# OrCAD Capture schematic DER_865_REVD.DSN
size D
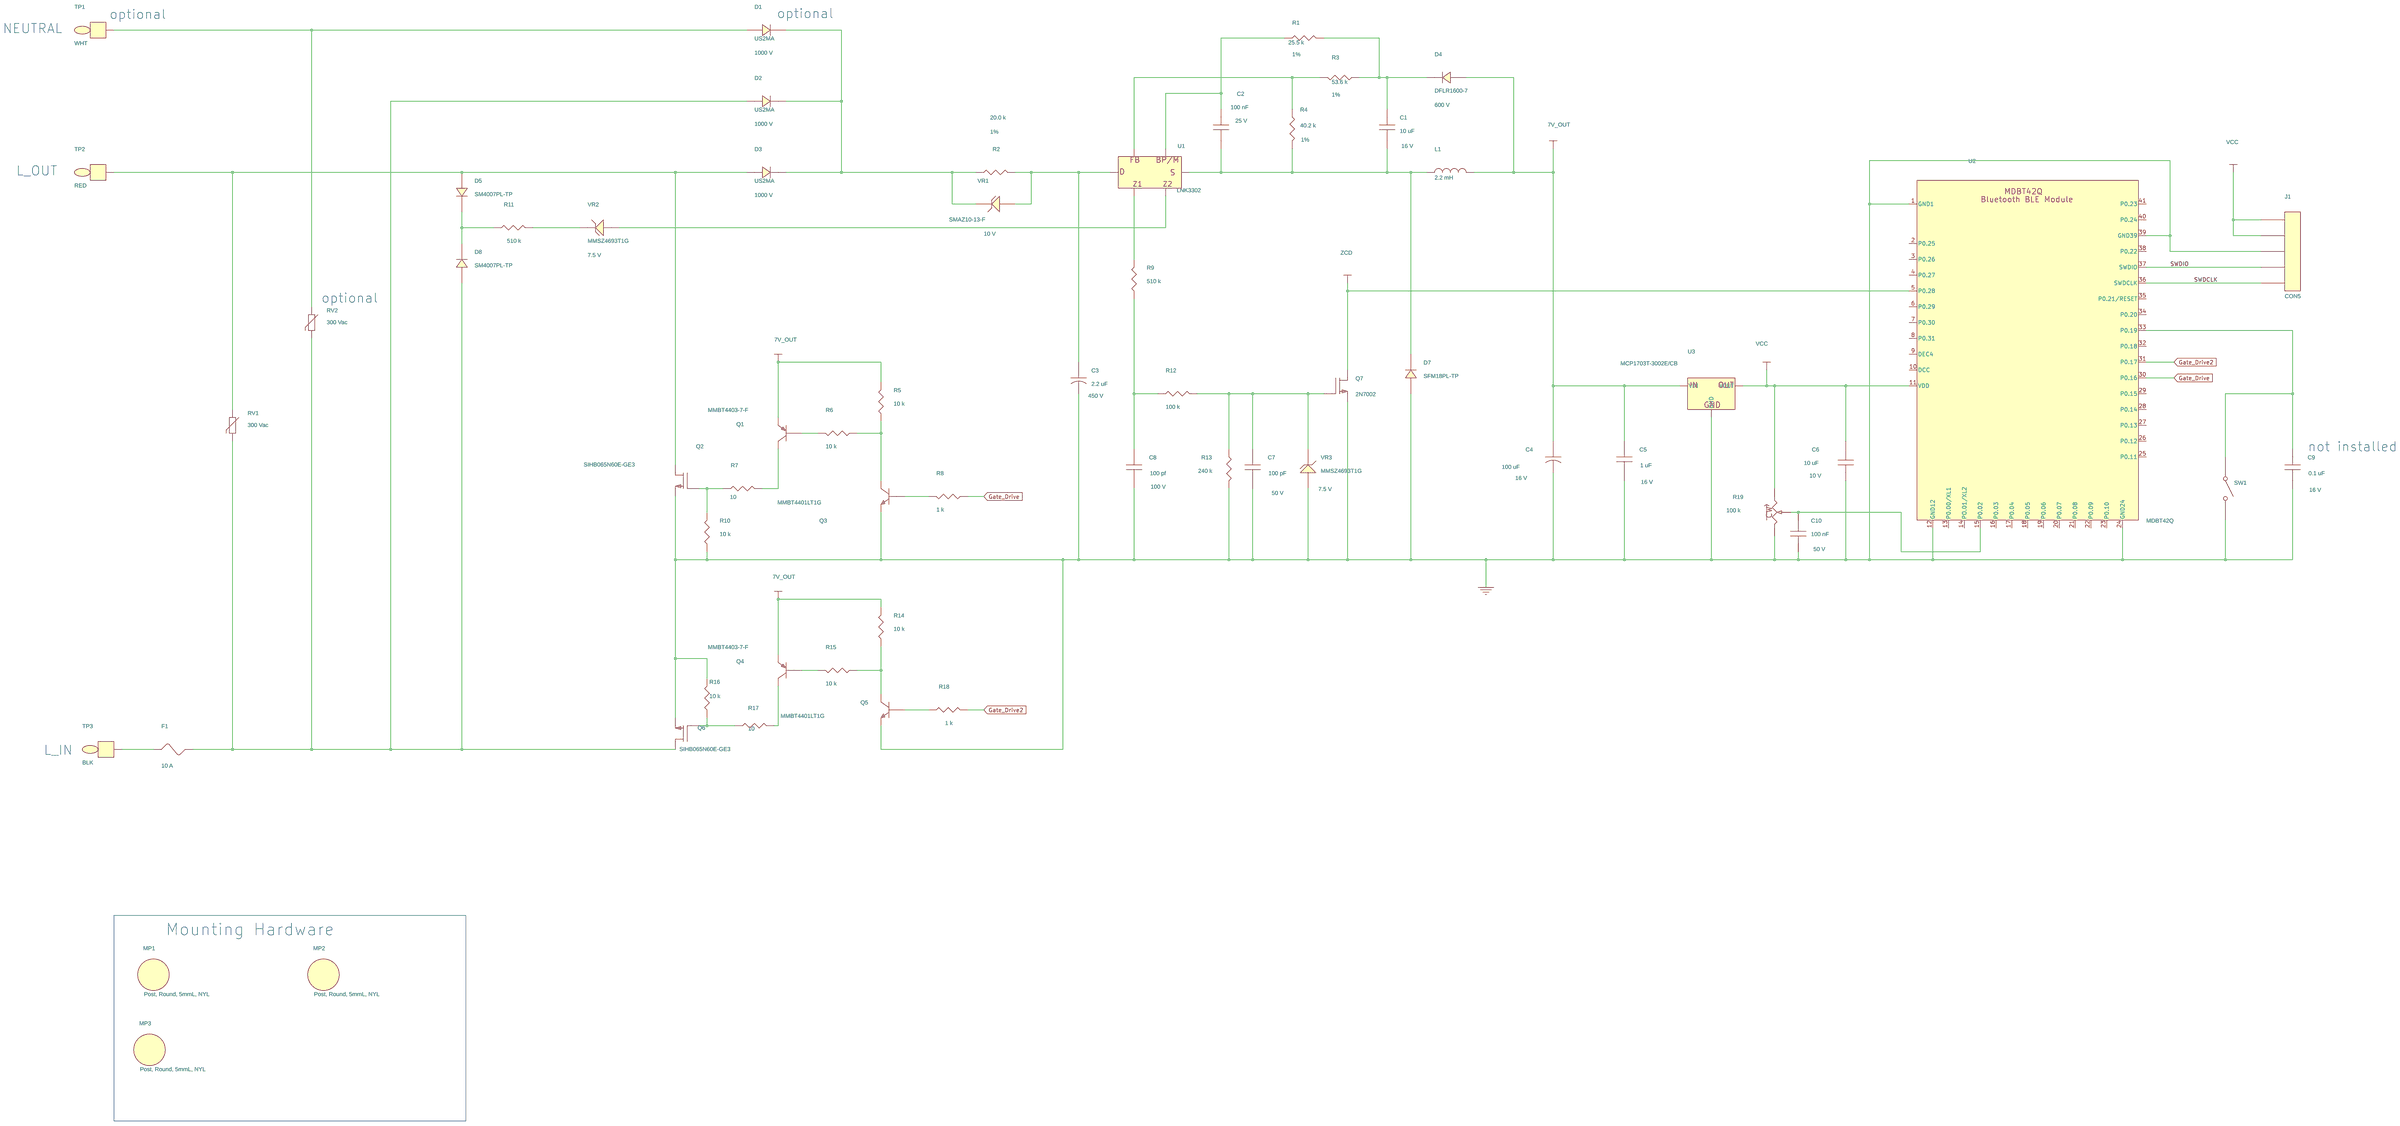
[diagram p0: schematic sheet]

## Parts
C1  10 uF  [pismc0805]
C2  100 nF  [pismc0805]
C3  2.2 uF  [pipolcapclyd320ls140030]
C4  100 uF  [pipolcapcyld250ls100030]
C5  1 uF  [pismc0805]
C6  10 uF  [pismc0805]
C7  100 pF  [pismc0603]
C8  100 pf  [pismc0805]
C9  0.1 uF  [pismc0805]
C10  100 nF  [pismc0603]
D1  US2MA  [pismdo214ac12]
D2  US2MA  [pismdo214ac12]
D3  US2MA  [pismdo214ac12]
D4  DFLR1600-7  [pismddflr120012]
D5  SM4007PL-TP  [pi_sm_sod-123_12]
D7  SFM18PL-TP  [pi_sm_sod-123_12]
D8  SM4007PL-TP  [pi_sm_sod-123_12]
F1  10 A  [pismFuse10p1x3p0]
J1  CON5  [pi_molex_5]
L1  2.2 mH  [pi_choke_2p_ls200d300]
MP1  Post, Round, 5mmL, NYL  [piSRSpacer_d125]
MP2  Post, Round, 5mmL, NYL  [piSRSpacer_d125]
MP3  Post, Round, 5mmL, NYL  [piSRSpacer_d125]
Q1  MMBT4403-7-F  [pismsot23123_1]
Q2  SIHB065N60E-GE3  [pismdd2pak]
Q3  MMBT4401LT1G  [pismsot23123_1]
Q4  MMBT4403-7-F  [pismsot23123_1]
Q5  MMBT4401LT1G  [pismsot23123_1]
Q6  SIHB065N60E-GE3  [pismdd2pak]
Q7  2N7002  [pismsot23123_1]
R1  25.5 k  [pismr0805]
R2  20.0 k  [pismr1206]
R3  53.6 k  [pismr0805]
R4  40.2 k  [pismr0805]
R5  10 k  [pismr0603]
R6  10 k  [pismr0603]
R7  10  [pismr0805]
R8  1 k  [pismr0603]
R9  510 k  [pismr0805]
R10  10 k  [pismr0805]
R11  510 k  [pismr0805]
R12  100 k  [pismr0805]
R13  240 k  [pismr0603]
R14  10 k  [pismr0603]
R15  10 k  [pismr0603]
R16  10 k  [pismr0805]
R17  10  [pismr0805]
R18  1 k  [pismr0603]
R19  100 k  [pivres9mmsquare]
RV1  300 Vac  [pidisc350x225ls240x140040]
RV2  300 Vac  [pidisc350x225ls240x140040]
SW1  SPST Toggle  [PI_SW_SPST_A11HP]
TP1  WHT  [pitpkeystone125x125]
TP2  RED  [pitpkeystone125x125]
TP3  BLK  [pitpkeystone125x125]
U1  LNK3302  [pismso8_nop3]
U2  MDBT42Q  [pi_Mod_Raytac_MDBT42Q]
U3  MCP1703T-3002E/CB  [pismsot23132]
VR1  SMAZ10-13-F  [pismdo214ac12]
VR2  MMSZ4693T1G  [pi_sm_sod-123_12]
VR3  MMSZ4693T1G  [pi_sm_sod-123_12]

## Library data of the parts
C1 = CAP_NP: Disp_Voltage: 16 V; Part Number: 20-08964-00; Voltage: 16 V
C2 = CAP_NP: Disp_Voltage: 25 V; Part Number: 20-08599-00; Voltage: 25 V
C3 = CAP_POL: Disp_Voltage: 450 V; FPLIST: pipolcapclyd320ls140030,pipolcapclyd320ls140030430h; Part Number: 20-08936-00; Voltage: 450 V
C4 = CAP_POL: ALT_SYMBOLS: pipolcapcyld250ls100030h; Disp_Voltage: 16 V; FPLIST: pipolcapcyld250ls100030,pipolcapcyld250ls100030h; Part Number: 20-00079-00; Voltage: 16 V
C5 = CAP_NP: Disp_Voltage: 16 V; Part Number: 20-01331-00; Voltage: 16 V
C6 = CAP_NP: Disp_Voltage: 10 V; Part Number: 20-01021-00; ROOM: 4; Voltage: 10 V
C7 = CAP_NP: Disp_Voltage: 50 V; Part Number: 20-01025-00; Voltage: 50 V
C8 = CAP_NP: Disp_Voltage: 100 V; Part Number: 24-00030-00; Voltage: 100 V
C9 = CAP_NP: Disp_Voltage: 16 V; Part Number: 20-09164-00; Voltage: 16 V
C10 = CAP_NP: Disp_Voltage: 50 V; Part Number: 20-00936-00; Voltage: 50 V
D1-D3 = DIODE: Disp_Voltage: 1000 V; Part Number: 15-016817-00
D4 = DIODE: Disp_Voltage: 600 V; Part Number: 15-00826-00
D5 D8 = DIODE: Part Number: 15-01070-00
D7 = DIODE: Part Number: 15-01634-00
F1 = FUSE: Part Number: 40-00088-00
J1 = CON5: ALT_SYMBOLS: berg_ps2_54_p5; FPLIST: pi_molex_5,berg_ps2_54_p5; Part Number: 35-00010-00
L1 = INDUCTOR: Part Number: 30-00384-00
MP1-MP3 = SelfRetainingSpacer_3mmhole: Part Number: 76-00040-00
Q1 Q4 = PNP_BEC: Part Number: 55-00060-00
Q2 Q6 = FET_N_GDS: Part Number: 50-00337-00
Q3 Q5 = NPN_BEC: Part Number: 55-00152-00
Q7 = FET_N_GSD: Part Number: 50-00103-00
R1 = R: Disp_Tol: 1%; Part Number: 05-00723-00
R2 = R: Disp_Tol: 1%; Part Number: 05-00318-00
R3 = R: Disp_Tol: 1%; Part Number: 05-00754-00
R4 = R: Disp_Tol: 1%; Part Number: 05-00742-00; Tol: 1%
R5 R6 R14 R15 = R: Part Number: 05-01712-00; ROOM: 2
R7 R17 = R: Part Number: 05-01471-00; ROOM: 2
R8 R18 = R: Part Number: 05-01688-00; ROOM: 2
R9 R11 = R: Part Number: 05-01584-00
R10 R16 = R: Part Number: 05-01543-00; ROOM: 2
R12 = R: Part Number: 05-01567-00
R13 = R: Part Number: 05-01745-00
R19 = POT: Part Number: 05-03498-00
RV1 RV2 = VARISTOR: Part Number: 85-00031-00
SW1 = SW_SPST: Part Number: 66-00402-00
TP1 = TESTPOINT: Part Number: 35-00044-00
TP2 = TESTPOINT: Part Number: 35-00043-00
TP3 = TESTPOINT: Part Number: 35-00042-00
U1 = LNK-TNZ: Part Number: 10-01234-00
U2 = Mod_Raytac_MDBT42Q: Part Number: 66-00255-00
U3 = MCP1754ST: Part Number: 45-00572-00
VR1 = DIODE_ZENER: Disp_Voltage: 10 V; Part Number: 15-01323-00
VR2 VR3 = DIODE_ZENER: Disp_Voltage: 7.5 V; Part Number: 15-01578-00

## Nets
7V_OUT: C4.1 C5.1 D4.2 L1.2 Q1.2(EMITTER) Q4.2(EMITTER) R5.2 R14.2 U3.3(VIN)
GND POWER: C3.2 C4.2 C5.2 C6.1 C7.2 C8.2 C9.2 C10.1 D7.2 J1.3 Q2.3(S) Q3.2(EMITTER) Q5.2(EMITTER) Q6.3(S) Q7.2(S) R10.1 R13.2 R16.2 R19.1(CCW) SW1.2 U2.1(GND1) U2.12(GND12) U2.24(GND24) U2.39(GND39) U3.1(GND) VR3.2
VCC: C6.2 J1.1 J1.2 R19.3(CW) U2.11(VDD) U3.2(VOUT)
Gate_Drive: R8.1 U2.30(P0.16)
Gate_Drive2: R18.1 U2.31(P0.17)
SWDCLK: J1.5 U2.36(SWDCLK)
SWDIO: J1.4 U2.37(SWDIO)
ZCD: Q7.3(D) U2.5(P0.28)
N140484: C3.1 R2.1 U1.4 VR1.2
N166085: D1.1 D2.1 D3.1 R2.2 VR1.1
N172951: F1.1 TP3.1
N285805: D3.2 D5.2 Q2.2(D) RV1.1 TP2.1
N295950: Q2.1(G) R7.1 R10.2
N325463: C1.2 C2.2 D7.1 L1.1 R4.2 U1.5
N325534: C2.1 R1.1 U1.7
N325998: C1.1 D4.1 R1.2 R3.1
N326030: R3.2 R4.1 U1.8
N328031: C9.1 SW1.1 U2.33(P0.19)
N332898: D2.2 D8.2 F1.2 Q6.2(D) RV1.2 RV2.2
N332994: Q6.1(G) R16.1 R17.1
N347733: D5.1 D8.1 R11.2
N354057: Q4.3(COLLECTOR) R17.2
N356858: Q1.3(COLLECTOR) R7.2
N356862: Q3.1(BASE) R8.2
N359869: Q1.1(BASE) R6.2
N360268: Q3.3(COLLECTOR) R5.1 R6.1
N361747: Q4.1(BASE) R15.2
N361751: Q5.3(COLLECTOR) R14.1 R15.1
N361818: Q5.1(BASE) R18.2
N547065: U1.2 VR2.2
N551285: C7.1 Q7.1(G) R12.2 R13.1 VR3.1
N551708: C8.1 R9.2 R12.1
N554020: R11.1 VR2.1
N554702: R9.1 U1.1
N560995: D1.2 RV2.1 TP1.1
N578362: C10.2 R19.2(WIPER) U2.15(P0.02)

Not connected (* = marked no-connect by the designer): MP1 1; MP2 1; MP3 1; U1 6; U2 2(P0.25) 3(P0.26) 4(P0.27) 6(P0.29) 7(P0.30) 8(P0.31) 9(DEC4) 10(DCC) 13(P0.00/XL1) 14(PO.01/XL2) 16(P0.03) 17(P0.04) 18(P0.05) 19(P0.06) 20(P0.07) 21(P0.08) 22(P0.09) 23(P0.10) 25(P0.11) 26(P0.12) 27(P0.13) 28(P0.14) 29(P0.15) 32(P0.18) 34(P0.20) 35(P0.21/RESET) 38(P0.22) 40(P0.24) 41(P0.23)

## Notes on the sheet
- optional
- optional
- NEUTRAL
- L_OUT
- optional
- not installed
- L_IN
- Mounting Hardware
